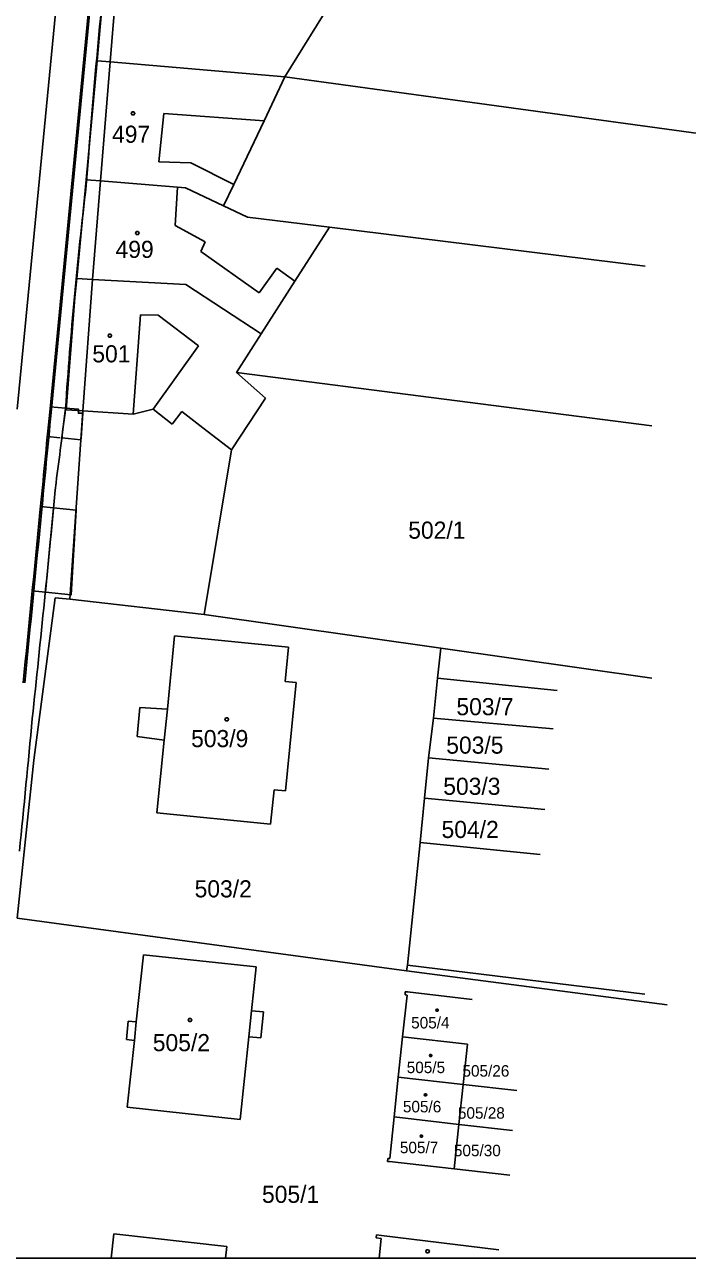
# Model space of a CAD drawing. Extents: x -639621 to -639329, y -1192893 to -1192488.
# Drawn here: x -639498.9 to -639433, y -1192893.3 to -1192770.8 of the extents above; entities that cross this region are included whole.
import ezdxf

# ---------------------------------------------------------------- set-up
doc = ezdxf.new("R2010")
doc.units = 0
for name, color, linetype in [('Vrstva 1', 7, 'Continuous'), ('Vrstva 19', 7, 'Continuous'), ('Vrstva 2', 7, 'Continuous'), ('Vrstva 20', 7, 'Continuous'), ('Vrstva 4', 7, 'Continuous'), ('Vrstva 5', 7, 'Continuous'), ('Vrstva 61', 7, 'Continuous')]:
    doc.layers.add(name, color=color, linetype=linetype)

msp = doc.modelspace()

# ---------------------------------------------------------------- linework, layer by layer
at = {"layer": 'Vrstva 1'}
for p, q in [((-639490.57, -1192761.34), (-639491.69, -1192774.35)), ((-639473.03, -1192775.94), (-639465.28, -1192763.39)), ((-639491.69, -1192774.35), (-639492.8, -1192786.16)), ((-639491.69, -1192774.35), (-639490.4, -1192774.46)), ((-639473.03, -1192775.94), (-639490.4, -1192774.46)), ((-639473.03, -1192775.94), (-639475.11, -1192780.31)), ((-639425.4, -1192782.45), (-639473.03, -1192775.94)), ((-639475.11, -1192780.31), (-639478.12, -1192786.62)), ((-639492.8, -1192786.16), (-639493.73, -1192795.97)), ((-639491.37, -1192786.28), (-639492.8, -1192786.16)), ((-639491.37, -1192786.28), (-639483.72, -1192786.91)), ((-639478.12, -1192786.62), (-639479.14, -1192788.77)), ((-639483.72, -1192786.91), (-639482.92, -1192786.98)), ((-639482.92, -1192786.98), (-639479.14, -1192788.77)), ((-639479.14, -1192788.77), (-639476.76, -1192789.89)), ((-639476.76, -1192789.89), (-639468.6, -1192790.89)), ((-639468.6, -1192790.89), (-639472.03, -1192796.23)), ((-639468.6, -1192790.89), (-639437.21, -1192794.75)), ((-639493.73, -1192795.97), (-639493.91, -1192797.87)), ((-639492.15, -1192796.06), (-639493.73, -1192795.97)), ((-639492.15, -1192796.06), (-639482.87, -1192796.56)), ((-639472.03, -1192796.23), (-639475.39, -1192801.48)), ((-639482.87, -1192796.56), (-639475.39, -1192801.48)), ((-639493.91, -1192797.87), (-639494.79, -1192809.03)), ((-639475.39, -1192801.48), (-639477.86, -1192805.33)), ((-639477.86, -1192805.33), (-639474.95, -1192807.86)), ((-639436.55, -1192810.6), (-639477.86, -1192805.33)), ((-639474.95, -1192807.86), (-639478.34, -1192813)), ((-639493.12, -1192809.14), (-639494.79, -1192809.03)), ((-639494.4, -1192827.84), (-639493.12, -1192809.14)), ((-639478.34, -1192813), (-639481.06, -1192829.36)), ((-639495.88, -1192827.71), (-639497.98, -1192843.85)), ((-639494.4, -1192827.84), (-639495.88, -1192827.71)), ((-639481.06, -1192829.36), (-639494.4, -1192827.84)), ((-639457.54, -1192832.71), (-639481.06, -1192829.36)), ((-639484.72, -1192838.77), (-639484, -1192831.47)), ((-639484, -1192831.47), (-639472.68, -1192832.62)), ((-639472.68, -1192832.62), (-639473.02, -1192836.01)), ((-639457.54, -1192832.71), (-639457.85, -1192835.68)), ((-639436.55, -1192835.69), (-639457.54, -1192832.71)), ((-639457.85, -1192835.68), (-639458.27, -1192839.66)), ((-639457.85, -1192835.68), (-639445.97, -1192836.92)), ((-639473.02, -1192836.01), (-639471.91, -1192836.12)), ((-639471.91, -1192836.12), (-639472.99, -1192846.89)), ((-639487.71, -1192841.49), (-639487.45, -1192838.59)), ((-639487.45, -1192838.59), (-639484.72, -1192838.77)), ((-639458.27, -1192839.66), (-639458.75, -1192843.61)), ((-639458.27, -1192839.66), (-639446.36, -1192840.72)), ((-639485.03, -1192841.85), (-639487.71, -1192841.49)), ((-639485.76, -1192849.08), (-639485.03, -1192841.85)), ((-639497.98, -1192843.85), (-639499.64, -1192859.54)), ((-639458.75, -1192843.61), (-639459.16, -1192847.61)), ((-639446.78, -1192844.73), (-639458.75, -1192843.61)), ((-639474.11, -1192846.77), (-639474.46, -1192850.2)), ((-639472.99, -1192846.89), (-639474.11, -1192846.77)), ((-639459.16, -1192847.61), (-639459.6, -1192852)), ((-639459.16, -1192847.61), (-639447.19, -1192848.75)), ((-639474.46, -1192850.2), (-639485.76, -1192849.08)), ((-639459.6, -1192852), (-639460.84, -1192864.19)), ((-639459.6, -1192852), (-639447.65, -1192853.2)), ((-639460.93, -1192864.78), (-639499.64, -1192859.54)), ((-639487.1, -1192863.17), (-639487.81, -1192869.85)), ((-639475.88, -1192864.37), (-639487.1, -1192863.17)), ((-639476.34, -1192868.73), (-639475.88, -1192864.37)), ((-639460.84, -1192864.19), (-639460.93, -1192864.78)), ((-639460.93, -1192864.78), (-639435.01, -1192868.14)), ((-639437.25, -1192867.1), (-639460.84, -1192864.19)), ((-639461.33, -1192871.31), (-639460.89, -1192867.17)), ((-639461.09, -1192867.15), (-639461.06, -1192866.85)), ((-639461.09, -1192867.15), (-639460.89, -1192867.17)), ((-639460.86, -1192866.87), (-639461.06, -1192866.85)), ((-639454.41, -1192867.62), (-639460.86, -1192866.87)), ((-639475.15, -1192868.85), (-639476.34, -1192868.73)), ((-639488.6, -1192869.77), (-639488.79, -1192871.6)), ((-639487.81, -1192869.85), (-639488.6, -1192869.77)), ((-639475.42, -1192871.43), (-639475.15, -1192868.85)), ((-639488.79, -1192871.6), (-639488, -1192871.69)), ((-639488, -1192871.69), (-639488.7, -1192878.32)), ((-639477.47, -1192879.53), (-639476.61, -1192871.31)), ((-639476.61, -1192871.31), (-639475.42, -1192871.43)), ((-639461.76, -1192875.34), (-639461.33, -1192871.31)), ((-639461.33, -1192871.31), (-639454.88, -1192872.05)), ((-639454.88, -1192872.05), (-639455.31, -1192876.05)), ((-639462.17, -1192879.28), (-639461.76, -1192875.34)), ((-639455.31, -1192876.05), (-639461.76, -1192875.34)), ((-639455.31, -1192876.05), (-639455.73, -1192880.02)), ((-639449.96, -1192876.65), (-639455.31, -1192876.05)), ((-639488.7, -1192878.32), (-639477.47, -1192879.53)), ((-639462.61, -1192883.42), (-639462.17, -1192879.28)), ((-639462.17, -1192879.28), (-639455.73, -1192880.02)), ((-639455.73, -1192880.02), (-639456.21, -1192884.44)), ((-639455.73, -1192880.02), (-639450.4, -1192880.62)), ((-639462.84, -1192883.7), (-639462.81, -1192883.4)), ((-639462.81, -1192883.4), (-639462.61, -1192883.42)), ((-639462.84, -1192883.7), (-639462.64, -1192883.72)), ((-639456.21, -1192884.44), (-639462.64, -1192883.72)), ((-639450.67, -1192885.06), (-639456.21, -1192884.44)), ((-639490.05, -1192890.89), (-639490.31, -1192893.33)), ((-639478.82, -1192892.16), (-639490.05, -1192890.89)), ((-639463.92, -1192891), (-639463.95, -1192891.3)), ((-639463.95, -1192891.3), (-639463.45, -1192891.35)), ((-639463.42, -1192891.05), (-639463.92, -1192891)), ((-639463.66, -1192893.33), (-639463.45, -1192891.35)), ((-639463.42, -1192891.05), (-639451.76, -1192892.5)), ((-639478.95, -1192893.33), (-639478.82, -1192892.16))]:
    msp.add_line(p, q, dxfattribs=at)
at = {"layer": 'Vrstva 19'}
msp.add_line((-639492.31, -1192766.82), (-639496.42, -1192809.27), dxfattribs=at)
msp.add_lwpolyline([(-639495.55, -1192766.51), (-639499.66, -1192808.96)], dxfattribs=at)
for centre, radius, start, end in [((-654430.04, -1191365.48), 15003.25, 354.439585, 354.477782), ((-646965.2, -1192091.38), 7503.2, 354.303419, 354.433219)]:
    msp.add_arc(centre, radius, start, end, dxfattribs=at)
at = {"layer": 'Vrstva 20'}
for p, q in [((-639492.17, -1192766.84), (-639496.27, -1192809.29)), ((-639494.84, -1192808.87), (-639496.37, -1192808.72)), ((-639495.37, -1192811.81), (-639496.66, -1192811.69)), ((-639496.03, -1192818.76), (-639497.33, -1192818.63)), ((-639496.85, -1192827.14), (-639498.15, -1192827.01))]:
    msp.add_line(p, q, dxfattribs=at)
for points in [[(-639495.21, -1192811.82), (-639493.31, -1192811.99), (-639493.3, -1192811.85), (-639493.12, -1192809.37), (-639493.57, -1192809.37), (-639493.55, -1192808.97), (-639494.84, -1192808.87)], [(-639496.85, -1192827.14), (-639494.27, -1192827.4), (-639493.77, -1192818.98), (-639496.03, -1192818.76), (-639496.44, -1192822.95)]]:
    msp.add_lwpolyline(points, close=True, dxfattribs=at)
for centre, radius, start, end in [((-638654.03, -1192849.48), 841.1, 173.99563, 175.72118), ((-639079.22, -1192836.38), 416.53, 173.1548, 176.2138), ((-654430.04, -1191365.48), 15003.4, 354.439585, 354.477782), ((-641212.11, -1192592.42), 1730.86, 352.56925, 352.81604), ((-641512.05, -1192624.91), 2025.32, 353.91214, 354.57847), ((-646965.2, -1192091.38), 7503.35, 354.303419, 354.433219), ((-641337.4, -1192667.87), 1847.26, 354.25167, 354.66271)]:
    msp.add_arc(centre, radius, start, end, dxfattribs=at)
at = {"layer": 'Vrstva 4'}
for p, q in [((-639490.4, -1192774.46), (-639489.32, -1192761.47)), ((-639490.4, -1192774.46), (-639491.37, -1192786.28)), ((-639485.08, -1192779.59), (-639485.56, -1192784.4)), ((-639485.08, -1192779.59), (-639475.11, -1192780.31)), ((-639485.56, -1192784.4), (-639482.37, -1192784.49)), ((-639482.37, -1192784.49), (-639478.12, -1192786.62)), ((-639491.37, -1192786.28), (-639492.15, -1192796.06)), ((-639483.72, -1192786.91), (-639483.93, -1192790.72)), ((-639483.93, -1192790.72), (-639480.97, -1192792.33)), ((-639480.97, -1192792.33), (-639481.4, -1192793.29)), ((-639481.4, -1192793.29), (-639475.59, -1192797.41)), ((-639473.84, -1192794.95), (-639475.59, -1192797.41)), ((-639472.03, -1192796.23), (-639473.84, -1192794.95)), ((-639492.15, -1192796.06), (-639493.12, -1192809.14)), ((-639487.4, -1192799.57), (-639488.13, -1192809.47)), ((-639485.63, -1192799.61), (-639487.4, -1192799.57)), ((-639481.64, -1192802.68), (-639485.63, -1192799.61)), ((-639486.14, -1192808.97), (-639481.64, -1192802.68)), ((-639488.13, -1192809.47), (-639493.12, -1192809.14)), ((-639488.13, -1192809.47), (-639486.14, -1192808.97)), ((-639486.14, -1192808.97), (-639484.23, -1192810.44)), ((-639484.23, -1192810.44), (-639483.28, -1192809.2)), ((-639481.19, -1192810.81), (-639483.28, -1192809.2)), ((-639478.34, -1192813), (-639481.19, -1192810.81)), ((-639484.72, -1192838.77), (-639485.03, -1192841.85)), ((-639476.34, -1192868.73), (-639476.61, -1192871.31)), ((-639488, -1192871.69), (-639487.81, -1192869.85))]:
    msp.add_line(p, q, dxfattribs=at)
at = {"layer": 'Vrstva 5'}
for points in [[(-639488.04, -1192779.43), (-639487.95, -1192779.58), (-639488.04, -1192779.73), (-639488.22, -1192779.73), (-639488.31, -1192779.58), (-639488.22, -1192779.43)], [(-639487.62, -1192791.32), (-639487.53, -1192791.47), (-639487.62, -1192791.62), (-639487.8, -1192791.62), (-639487.89, -1192791.47), (-639487.8, -1192791.32)], [(-639490.35, -1192801.5), (-639490.26, -1192801.65), (-639490.35, -1192801.8), (-639490.53, -1192801.8), (-639490.62, -1192801.65), (-639490.53, -1192801.5)], [(-639478.72, -1192839.63), (-639478.63, -1192839.78), (-639478.72, -1192839.93), (-639478.9, -1192839.93), (-639478.99, -1192839.78), (-639478.9, -1192839.63)], [(-639457.84, -1192868.58), (-639457.78, -1192868.68), (-639457.84, -1192868.78), (-639457.96, -1192868.78), (-639458.02, -1192868.68), (-639457.96, -1192868.58)], [(-639482.38, -1192869.5), (-639482.29, -1192869.65), (-639482.38, -1192869.8), (-639482.56, -1192869.8), (-639482.65, -1192869.65), (-639482.56, -1192869.5)], [(-639458.48, -1192873.08), (-639458.42, -1192873.18), (-639458.48, -1192873.28), (-639458.6, -1192873.28), (-639458.66, -1192873.18), (-639458.6, -1192873.08)], [(-639458.99, -1192876.99), (-639458.93, -1192877.09), (-639458.99, -1192877.19), (-639459.11, -1192877.19), (-639459.17, -1192877.09), (-639459.11, -1192876.99)], [(-639459.4, -1192881.08), (-639459.34, -1192881.18), (-639459.4, -1192881.28), (-639459.52, -1192881.28), (-639459.58, -1192881.18), (-639459.52, -1192881.08)], [(-639458.76, -1192892.48), (-639458.67, -1192892.63), (-639458.76, -1192892.78), (-639458.94, -1192892.78), (-639459.03, -1192892.63), (-639458.94, -1192892.48)]]:
    msp.add_lwpolyline(points, close=True, dxfattribs=at)
at = {"layer": 'Vrstva 61'}
msp.add_lwpolyline([(-639329.26, -1192893.33), (-639621.26, -1192893.33)], dxfattribs=at)

# ---------------------------------------------------------------- texts
at = {"layer": 'Vrstva 2'}
for s, height, p in [('497', 1.7, (-639490.22, -1192782.49)), ('499', 1.7, (-639489.87, -1192793.93)), ('501', 1.7, (-639492.18, -1192804.31)), ('502/1', 1.7, (-639460.77, -1192821.83)), ('503/7', 1.7, (-639455.98, -1192839.37)), ('503/9', 1.7, (-639482.36, -1192842.54)), ('503/5', 1.7, (-639456.99, -1192843.19)), ('503/3', 1.7, (-639457.29, -1192847.28)), ('504/2', 1.7, (-639457.46, -1192851.57)), ('503/2', 1.7, (-639482.01, -1192857.47)), ('505/4', 1.14, (-639460.48, -1192870.49)), ('505/2', 1.7, (-639486.17, -1192872.75)), ('505/5', 1.14, (-639460.92, -1192874.93)), ('505/26', 1.14, (-639455.38, -1192875.28)), ('505/6', 1.14, (-639461.3, -1192878.83)), ('505/28', 1.14, (-639455.83, -1192879.46)), ('505/7', 1.14, (-639461.6, -1192882.89)), ('505/30', 1.14, (-639456.23, -1192883.19)), ('505/1', 1.7, (-639475.31, -1192887.82))]:
    msp.add_text(s, height=height, dxfattribs=at).set_placement(p)

doc.saveas('drawing.dxf')
